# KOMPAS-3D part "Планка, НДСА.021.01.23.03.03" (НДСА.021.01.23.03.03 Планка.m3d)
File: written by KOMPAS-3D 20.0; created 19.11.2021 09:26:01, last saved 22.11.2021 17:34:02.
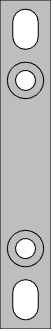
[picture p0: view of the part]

Document properties: Полное имя файла: C:\Users\s.pischagina\Desktop\PLM\НДСА.021.01.23.03.03 Планка.m3d

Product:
- Part/product: Планка  | designation НДСА.021.01.23.03.03
    Материал: АМг6  ГОСТ 4784-2019 (density 2640 kg/m3)
    Масса: 0.0267637
    additional columns: <item xmlns="http://appius.ru/pdm" xmlns:xs="http://www.w3.org/2001/XMLSchema" x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; <item xmlns="http://appius.ru/pdm" xmlns:xs="http://www.w3.org/2001/XMLSchema" x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; <item xmlns="http://appius.ru/pdm" xmlns:xs="http://www.w3.org/2001/XMLSchema" x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
    source file: НДСА.021.01.23.03.03 Планка.cdw

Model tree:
1. Эскиз:1
2. Элемент выдавливания:1
     Расстояние 1 = 10
3. Эскиз:2  (with: Элемент выдавливания:1)
4. Элемент выдавливания:2
     Расстояние 2 = 6
5. Эскиз:3  (with: Элемент выдавливания:1)
6. Элемент выдавливания:3  (labels: АМг6  ГОСТ 4784-2019)
     Расстояние 2 = 10

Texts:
  НДСА.021.01.23.03.03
